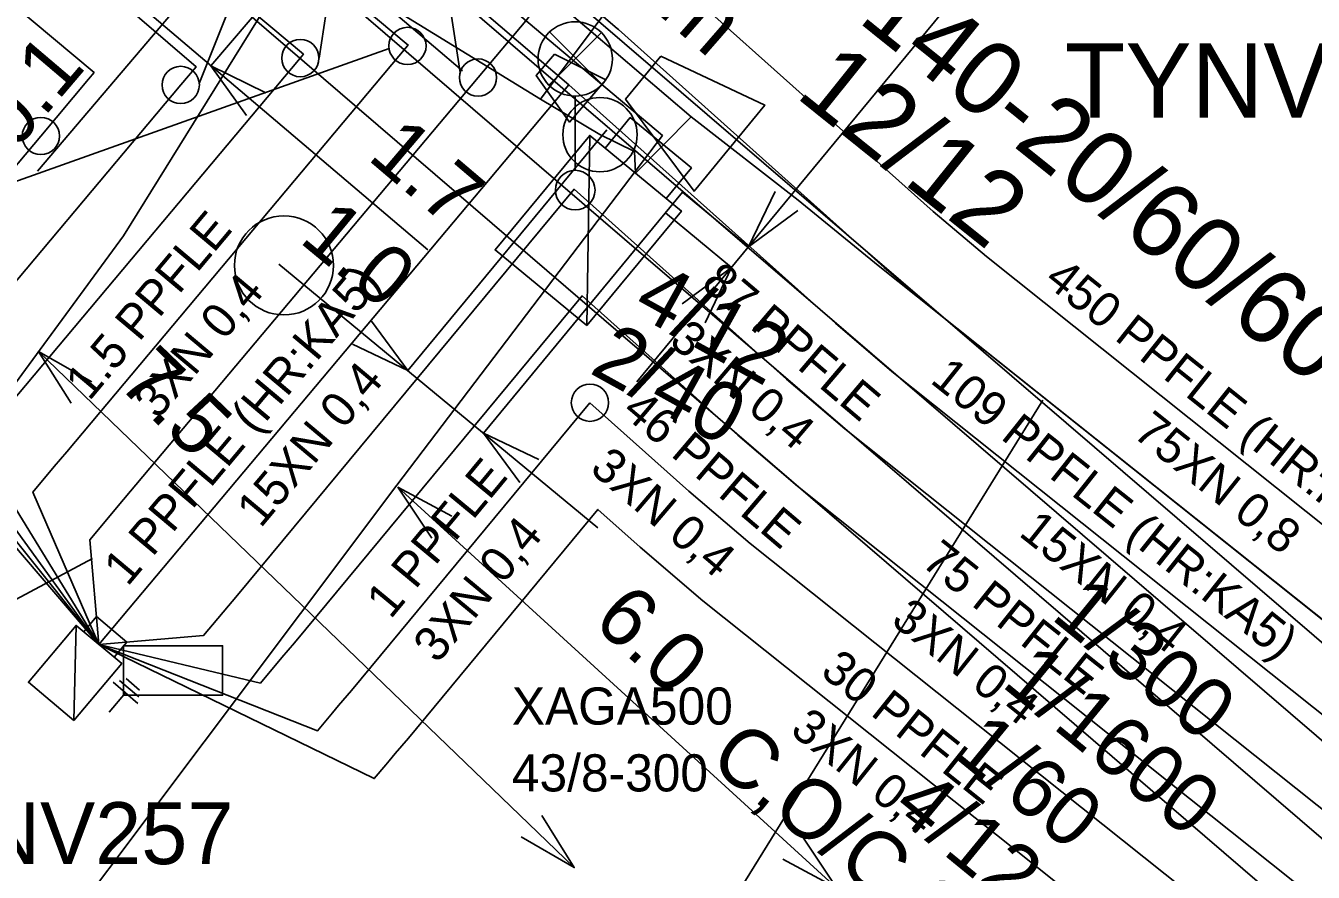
# Model space of a CAD drawing. Extents: x -756413 to -755757, y -1139003 to -1138237.
# Drawn here: x -756288.54 to -756275.54, y -1138383.61 to -1138375.06 of the extents above; entities that cross this region are included whole.
import ezdxf

# ---------------------------------------------------------------- set-up
doc = ezdxf.new("R2010")
doc.units = 0
for name, color, linetype in [('f002_inz_znacky_mimo_TO2', 7, 'Continuous'), ('f003_opt_sit_texty', 7, 'Continuous'), ('f004_popis_kab_zil', 7, 'Continuous'), ('f004_popisy_mts', 7, 'Continuous'), ('f004_rezervy_spojky', 7, 'Continuous'), ('f004_rozvadec', 7, 'Continuous'), ('f004_rozvadec_ann', 7, 'Continuous'), ('f006_osa_trasy', 7, 'Continuous'), ('f006_stp_koty', 7, 'Continuous'), ('f006_stp_linie', 7, 'Continuous'), ('f006_stp_texty', 7, 'Continuous'), ('f007_rezkynet_linie', 7, 'Continuous'), ('f307_kabel_metal', 7, 'Continuous'), ('f307_kabel_metal_ann', 7, 'Continuous'), ('f307_ost_bod_obj_met', 7, 'Continuous'), ('f307_rozvadec', 7, 'Continuous'), ('f307_rozvadec_ann', 7, 'Continuous'), ('f307_spojka_metal', 7, 'Continuous'), ('f307_spojka_metal_ann', 7, 'Continuous'), ('f309_trubka', 7, 'Continuous'), ('f373_cerch_cara', 7, 'Continuous')]:
    doc.layers.add(name, color=color, linetype=linetype)

msp = doc.modelspace()

# ---------------------------------------------------------------- linework, layer by layer
at = {"layer": 'f002_inz_znacky_mimo_TO2'}
for p, q in [((-756282.718, -1138375.655), (-756283.246, -1138375.126)), ((-756283.254, -1138375.658), (-756282.726, -1138375.13)), ((-756282.99, -1138375.77), (-756282.99, -1138376.52))]:
    msp.add_line(p, q, dxfattribs=at)
msp.add_lwpolyline([(-756287.55, -1138381.82), (-756286.55, -1138381.82), (-756286.55, -1138381.32), (-756287.55, -1138381.32)], close=True, dxfattribs=at)
for centre, radius in [((-756282.99, -1138375.395), 0.375), ((-756282.99, -1138376.72), 0.2), ((-756285.93, -1138377.48), 0.5)]:
    msp.add_circle(centre, radius, dxfattribs=at)
at = {"layer": 'f004_rezervy_spojky'}
msp.add_lwpolyline([(-756282.125, -1138375.366), (-756281.077, -1138375.862), (-756281.79, -1138376.732), (-756282.482, -1138375.801)], close=True, dxfattribs=at)
msp.add_circle((-756282.74, -1138376.16), 0.375, dxfattribs=at)
at = {"layer": 'f004_rozvadec'}
msp.add_line((-756282.873, -1138378.088), (-756282.843, -1138376.168), dxfattribs=at)
msp.add_lwpolyline([(-756282.688, -1138376.295), (-756282.434, -1138375.987), (-756281.817, -1138376.496), (-756282.072, -1138376.805)], dxfattribs=at)
msp.add_lwpolyline([(-756282.873, -1138378.088), (-756283.798, -1138377.324), (-756282.843, -1138376.168), (-756281.917, -1138376.932)], close=True, dxfattribs=at)
at = {"layer": 'f006_osa_trasy'}
for p, q in [((-756278.21, -1138368.9), (-756282.83, -1138375.12)), ((-756282.83, -1138375.12), (-756283.34, -1138375.8)), ((-756281.82, -1138375.98), (-756282.83, -1138375.12)), ((-756283.34, -1138375.8), (-756282.74, -1138376.16)), ((-756281.82, -1138375.98), (-756282.38, -1138376.55))]:
    msp.add_line(p, q, dxfattribs=at)
for points in [[(-756282.83, -1138375.12), (-756286.84, -1138371.72), (-756290.36, -1138368.73), (-756302.28, -1138358.38), (-756303.67, -1138357.72), (-756311.7, -1138350.6)], [(-756290.62, -1138387.46), (-756284.79, -1138379.7), (-756282.11, -1138376.17), (-756288.02, -1138371.19), (-756301.12, -1138358.98), (-756302.2, -1138358.1), (-756303.05, -1138358.15), (-756304.87, -1138359.66)], [(-756312.22, -1138404.34), (-756311.43, -1138403.06), (-756307.8, -1138399.78), (-756302.65, -1138394.53), (-756298.44, -1138390.08), (-756293.77, -1138384.84), (-756291.02, -1138381.91), (-756287.55, -1138377.18), (-756286, -1138374.68), (-756285.31, -1138374.59), (-756283.34, -1138375.8)], [(-756272.52, -1138383.39), (-756279.93, -1138377.48), (-756280.74, -1138376.82), (-756281.82, -1138375.98)], [(-756282.74, -1138376.16), (-756282.39, -1138376.33), (-756282.38, -1138376.55)]]:
    msp.add_lwpolyline(points, dxfattribs=at)
at = {"layer": 'f006_stp_koty'}
for p, q in [((-756289.262, -1138371.148), (-756284.127, -1138375.514)), ((-756288.418, -1138376.529), (-756285.145, -1138372.679)), ((-756284.479, -1138377.324), (-756289.103, -1138373.393)), ((-756282.367, -1138378.657), (-756278.169, -1138373.576)), ((-756286, -1138374.68), (-756286.667, -1138375.464)), ((-756282.67, -1138376.11), (-756284.681, -1138378.543)), ((-756281.907, -1138376.741), (-756283.917, -1138379.174)), ((-756281.907, -1138376.741), (-756281.239, -1138377.292)), ((-756282.08, -1138376.95), (-756281.412, -1138377.501)), ((-756285.981, -1138377.468), (-756282.761, -1138380.129)), ((-756283, -1138383.56), (-756288.408, -1138378.349)), ((-756280.35, -1138383.77), (-756284.779, -1138379.72))]:
    msp.add_line(p, q, dxfattribs=at)
for points in [[(-756286.307, -1138375.966), (-756286.667, -1138375.464), (-756286.112, -1138375.738)], [(-756280.741, -1138376.925), (-756281.239, -1138377.292), (-756280.972, -1138376.733)], [(-756281.909, -1138377.867), (-756281.412, -1138377.501), (-756281.678, -1138378.059)], [(-756285.047, -1138378.045), (-756284.681, -1138378.543), (-756285.239, -1138378.276)], [(-756288.079, -1138378.873), (-756288.408, -1138378.349), (-756287.871, -1138378.657)], [(-756283.55, -1138379.671), (-756283.917, -1138379.174), (-756283.358, -1138379.44)], [(-756284.437, -1138380.235), (-756284.779, -1138379.72), (-756284.234, -1138380.014)], [(-756283.328, -1138383.035), (-756283, -1138383.56), (-756283.536, -1138383.251)], [(-756280.691, -1138383.254), (-756280.35, -1138383.77), (-756280.894, -1138383.475)]]:
    msp.add_lwpolyline(points, dxfattribs=at)
at = {"layer": 'f006_stp_linie'}
msp.add_line((-756282.74, -1138376.16), (-756282.39, -1138376.33), dxfattribs=at)
for points in [[(-756278.21, -1138368.9), (-756282.83, -1138375.12), (-756283.34, -1138375.8)], [(-756286.84, -1138371.72), (-756282.83, -1138375.12), (-756281.82, -1138375.98), (-756280.74, -1138376.82)], [(-756325.53, -1138418.96), (-756324.32, -1138416.51), (-756322.61, -1138413.84), (-756321.49, -1138412.22), (-756320.41, -1138411.21), (-756318.19, -1138409.32), (-756315.85, -1138407.31), (-756315.25, -1138406.9), (-756313.95, -1138405.81), (-756312.72, -1138405.17), (-756312.44, -1138404.71), (-756312.22, -1138404.34), (-756311.43, -1138403.06), (-756307.8, -1138399.78), (-756302.65, -1138394.53), (-756298.44, -1138390.08), (-756293.77, -1138384.84), (-756291.02, -1138381.91), (-756287.55, -1138377.18), (-756286, -1138374.68), (-756285.31, -1138374.59), (-756283.34, -1138375.8), (-756282.74, -1138376.16)], [(-756279.93, -1138377.48), (-756272.52, -1138383.39), (-756268.72, -1138385.93), (-756262.4, -1138389.61), (-756257.5, -1138391.97), (-756251.81, -1138394.29), (-756243.07, -1138396.46), (-756234.47, -1138397.8), (-756219.38, -1138400.15), (-756214.62, -1138400.84), (-756208.37, -1138401.82)]]:
    msp.add_lwpolyline(points, dxfattribs=at)
at = {"layer": 'f007_rezkynet_linie'}
msp.add_line((-756286.89, -1138392.77), (-756278.27, -1138378.84), dxfattribs=at)
at = {"layer": 'f307_kabel_metal'}
for p, q in [((-756312.023, -1138350.844), (-756283.054, -1138375.657)), ((-756283.054, -1138375.657), (-756287.798, -1138381.308))]:
    msp.add_line(p, q, dxfattribs=at)
for points in [[(-756310.454, -1138350.213), (-756282.069, -1138374.526), (-756282.051, -1138374.542), (-756279.377, -1138376.935), (-756278.838, -1138377.392), (-756272.1, -1138382.766), (-756271.532, -1138383.148), (-756268.323, -1138385.294), (-756262.071, -1138388.934), (-756261.451, -1138389.235), (-756257.195, -1138391.284), (-756251.577, -1138393.575), (-756242.922, -1138395.724), (-756234.355, -1138397.059), (-756233.614, -1138397.174), (-756219.271, -1138399.407)], [(-756310.942, -1138350.783), (-756282.566, -1138375.087), (-756282.554, -1138375.098), (-756279.87, -1138377.5), (-756279.315, -1138377.971), (-756272.544, -1138383.371), (-756271.95, -1138383.771), (-756268.72, -1138385.93), (-756262.424, -1138389.596), (-756261.778, -1138389.91), (-756257.5, -1138391.97), (-756251.81, -1138394.29), (-756243.07, -1138396.46), (-756234.47, -1138397.8), (-756233.729, -1138397.915), (-756219.383, -1138400.149)], [(-756283.971, -1138375.583), (-756283.489, -1138375.009), (-756279.087, -1138369.245), (-756278.124, -1138370.005), (-756278.057, -1138370.064), (-756275.436, -1138372.41), (-756275.026, -1138372.757), (-756270.414, -1138376.436), (-756263.958, -1138368.536)], [(-756284.683, -1138375.264), (-756284.676, -1138375.255), (-756291.577, -1138369.478), (-756295.006, -1138373.564), (-756295.13, -1138373.711), (-756298.544, -1138377.773), (-756318.688, -1138398.187), (-756319.519, -1138397.43)], [(-756285.765, -1138375.387), (-756285.733, -1138375.348), (-756291.484, -1138370.534), (-756294.432, -1138374.047), (-756294.556, -1138374.194), (-756297.989, -1138378.278), (-756318.66, -1138399.227), (-756319.205, -1138399.742), (-756330.074, -1138410.117), (-756326.605, -1138419.746), (-756341.343, -1138432.472)], [(-756286.972, -1138375.658), (-756286.816, -1138375.476), (-756291.179, -1138371.724), (-756291.391, -1138371.59), (-756293.858, -1138374.53), (-756293.982, -1138374.677), (-756297.434, -1138378.783), (-756318.135, -1138399.763), (-756318.689, -1138400.286), (-756329.203, -1138410.322), (-756325.725, -1138419.977), (-756325.47, -1138420.682), (-756325.148, -1138421.576), (-756313.125, -1138448.388), (-756305.964, -1138469.586), (-756306.39, -1138472.389), (-756307.168, -1138474.638), (-756308.162, -1138475.59), (-756309.285, -1138475.849), (-756315.462, -1138479.353)], [(-756288.384, -1138376.174), (-756287.902, -1138375.6), (-756287.847, -1138375.534), (-756291.298, -1138372.646), (-756293.284, -1138375.013), (-756293.408, -1138375.16), (-756296.879, -1138379.289), (-756317.519, -1138400.206), (-756328.332, -1138410.527), (-756324.452, -1138421.295), (-756312.811, -1138447.256), (-756304.831, -1138441.703), (-756301.921, -1138444.882), (-756300.466, -1138443.292)], [(-756287.798, -1138381.308), (-756289.039, -1138379.287), (-756288.887, -1138379.105), (-756288.822, -1138379.029), (-756288.697, -1138378.88), (-756285.765, -1138375.387)], [(-756287.798, -1138381.308), (-756288.465, -1138379.769), (-756288.249, -1138379.512), (-756288.123, -1138379.363), (-756284.683, -1138375.264)], [(-756287.798, -1138381.308), (-756287.89, -1138380.251), (-756287.549, -1138379.845), (-756283.971, -1138375.583)], [(-756287.798, -1138381.308), (-756290.762, -1138377.84), (-756290.683, -1138377.744), (-756290.663, -1138377.72), (-756290.644, -1138377.699), (-756290.607, -1138377.654), (-756290.541, -1138377.576), (-756290.421, -1138377.434), (-756288.958, -1138375.692)], [(-756287.798, -1138381.308), (-756289.613, -1138378.805), (-756289.496, -1138378.664), (-756289.46, -1138378.621), (-756289.394, -1138378.544), (-756289.272, -1138378.398), (-756286.972, -1138375.658)], [(-756283.054, -1138375.657), (-756280.363, -1138378.065), (-756279.792, -1138378.55), (-756272.988, -1138383.976), (-756272.368, -1138384.394), (-756269.117, -1138386.566), (-756262.777, -1138390.258), (-756262.105, -1138390.585), (-756257.805, -1138392.656), (-756252.043, -1138395.005), (-756243.218, -1138397.196), (-756234.585, -1138398.541), (-756233.844, -1138398.656), (-756219.495, -1138400.891), (-756218.753, -1138400.999), (-756214.732, -1138401.582), (-756208.498, -1138402.559), (-756199.964, -1138404.184), (-756190.805, -1138406.292), (-756186.311, -1138407.813)], [(-756287.798, -1138381.308), (-756290.188, -1138378.322), (-756290.091, -1138378.206), (-756290.072, -1138378.184), (-756290.032, -1138378.136), (-756289.967, -1138378.059), (-756289.847, -1138377.916), (-756288.384, -1138376.174)], [(-756287.798, -1138381.308), (-756286.741, -1138381.216), (-756286.4, -1138380.81), (-756283.001, -1138376.711), (-756280.856, -1138378.63), (-756280.269, -1138379.129), (-756273.432, -1138384.581), (-756272.786, -1138385.017), (-756269.514, -1138387.202), (-756263.13, -1138390.92), (-756262.432, -1138391.26), (-756258.11, -1138393.342), (-756252.276, -1138395.72), (-756243.366, -1138397.932), (-756234.7, -1138399.282), (-756233.959, -1138399.397), (-756219.607, -1138401.633), (-756219.715, -1138403.938)], [(-756287.798, -1138381.308), (-756286.167, -1138381.698), (-756285.951, -1138381.441), (-756285.824, -1138381.291), (-756282.921, -1138377.789), (-756281.349, -1138379.195), (-756280.746, -1138379.708), (-756273.876, -1138385.186), (-756273.204, -1138385.64), (-756269.911, -1138387.839), (-756263.483, -1138391.582), (-756262.759, -1138391.935), (-756258.415, -1138394.028), (-756252.509, -1138396.435), (-756243.514, -1138398.668), (-756234.815, -1138400.023), (-756234.827, -1138399.997), (-756234.95, -1138400.65), (-756236.72, -1138403.56), (-756242.2, -1138408.96), (-756243.304, -1138410.025)], [(-756287.798, -1138381.308), (-756285.593, -1138382.18), (-756285.44, -1138381.998), (-756285.378, -1138381.925), (-756285.249, -1138381.773), (-756282.841, -1138378.867)], [(-756282.841, -1138378.867), (-756281.842, -1138379.76), (-756281.223, -1138380.287), (-756274.32, -1138385.791), (-756273.622, -1138386.263), (-756270.308, -1138388.476), (-756264.16, -1138392.056), (-756266.339, -1138395.376)], [(-756287.798, -1138381.308), (-756285.018, -1138382.662), (-756284.901, -1138382.522), (-756284.867, -1138382.482), (-756284.806, -1138382.41), (-756284.674, -1138382.255), (-756282.76, -1138379.945), (-756282.335, -1138380.325), (-756281.7, -1138380.866), (-756275.574, -1138385.75), (-756278.058, -1138387.734)]]:
    msp.add_lwpolyline(points, dxfattribs=at)
at = {"layer": 'f307_ost_bod_obj_met'}
for p, q in [((-756287.405, -1138381.904), (-756287.655, -1138381.69)), ((-756287.396, -1138381.836), (-756287.589, -1138381.671)), ((-756287.388, -1138381.768), (-756287.524, -1138381.653)), ((-756287.53, -1138381.797), (-756287.696, -1138381.991))]:
    msp.add_line(p, q, dxfattribs=at)
at = {"layer": 'f307_rozvadec'}
msp.add_line((-756288.05, -1138382.075), (-756288.028, -1138381.115), dxfattribs=at)
msp.add_lwpolyline([(-756287.951, -1138381.179), (-756287.823, -1138381.026), (-756287.516, -1138381.283), (-756287.645, -1138381.437)], dxfattribs=at)
msp.add_lwpolyline([(-756288.05, -1138382.075), (-756288.51, -1138381.69), (-756288.028, -1138381.115), (-756287.568, -1138381.501)], close=True, dxfattribs=at)
at = {"layer": 'f307_spojka_metal'}
msp.add_lwpolyline([(-756283.2, -1138375.347), (-756282.681, -1138375.606), (-756283.047, -1138376.033), (-756283.383, -1138375.561)], close=True, dxfattribs=at)
for centre in [(-756284.683, -1138375.264), (-756285.765, -1138375.387), (-756286.972, -1138375.658), (-756283.971, -1138375.583), (-756288.384, -1138376.174), (-756282.841, -1138378.867)]:
    msp.add_circle(centre, 0.188, dxfattribs=at)
at = {"layer": 'f309_trubka'}
for points in [[(-756310.552, -1138351.565), (-756303.608, -1138357.783), (-756301.98, -1138358.543), (-756289.41, -1138369.29), (-756273.581, -1138382.899), (-756267.391, -1138386.699), (-756260.769, -1138390.604), (-756251.313, -1138394.329), (-756242.348, -1138396.659), (-756226.133, -1138399.092), (-756211.588, -1138401.296), (-756190.711, -1138405.458), (-756180.192, -1138409.372), (-756170.888, -1138414.389), (-756161.932, -1138421.301), (-756154.261, -1138427.534)], [(-756311.061, -1138352.116), (-756304.026, -1138358.416), (-756302.39, -1138359.179), (-756289.898, -1138369.859), (-756274.024, -1138383.507), (-756267.778, -1138387.342), (-756261.099, -1138391.28), (-756251.546, -1138395.043), (-756242.498, -1138397.395), (-756226.245, -1138399.834), (-756211.718, -1138402.035), (-756190.916, -1138406.182), (-756180.502, -1138410.057), (-756171.298, -1138415.02), (-756162.398, -1138421.889), (-756154.878, -1138427.999)], [(-756311.57, -1138352.667), (-756304.444, -1138359.049), (-756302.8, -1138359.815), (-756290.386, -1138370.428), (-756274.468, -1138384.115), (-756268.165, -1138387.985), (-756261.429, -1138391.956), (-756251.779, -1138395.757), (-756242.648, -1138398.131), (-756226.357, -1138400.576), (-756211.848, -1138402.774), (-756191.121, -1138406.906), (-756180.812, -1138410.742), (-756171.708, -1138415.651), (-756162.864, -1138422.477), (-756155.495, -1138428.464)], [(-756312.079, -1138353.218), (-756304.862, -1138359.682), (-756303.21, -1138360.452), (-756290.874, -1138370.997), (-756274.912, -1138384.723), (-756268.552, -1138388.628), (-756261.759, -1138392.632), (-756252.012, -1138396.471), (-756242.798, -1138398.867), (-756226.469, -1138401.318), (-756211.978, -1138403.513), (-756191.326, -1138407.63), (-756181.122, -1138411.427), (-756172.118, -1138416.282), (-756163.33, -1138423.065), (-756156.112, -1138428.929), (-756154.994, -1138431.554)]]:
    msp.add_lwpolyline(points, dxfattribs=at)
at = {"layer": 'f373_cerch_cara'}
for p in [(-756286.785, -1138375.642), (-756285.576, -1138375.389)]:
    msp.add_line(p, (-756284.874, -1138370.831), dxfattribs=at)
for points in [[(-756284.151, -1138375.531), (-756284.874, -1138370.831), (-756281.608, -1138370.792)], [(-756284.867, -1138375.29), (-756290.484, -1138377.288), (-756290.935, -1138377.287)], [(-756287.861, -1138380.439), (-756291.887, -1138382.589), (-756295.017, -1138382.609)]]:
    msp.add_lwpolyline(points, dxfattribs=at)

# ---------------------------------------------------------------- texts
at = {"layer": 'f003_opt_sit_texty'}
msp.add_text('C,O/C,C/O', height=0.6, rotation=321.43, dxfattribs=at).set_placement((-756281.66, -1138382.51))
at = {"layer": 'f004_popis_kab_zil'}
for s, rotation, p in [('4/12', 331, (-756282.43, -1138377.95)), ('2/40', 331, (-756282.86, -1138378.56)), ('1/300', 320.67, (-756278.2, -1138381.04)), ('1/1600', 320.67, (-756278.7, -1138381.72)), ('1/60', 320.67, (-756279.2, -1138382.42)), ('4/12', 320.67, (-756279.81, -1138382.99))]:
    msp.add_text(s, height=0.6, rotation=rotation, dxfattribs=at).set_placement(p)
at = {"layer": 'f004_popisy_mts'}
for s, p in [('140-20/60/60', (-756280.15, -1138375.01)), ('12/12', (-756280.78, -1138375.77))]:
    msp.add_text(s, height=0.75, rotation=321.28, dxfattribs=at).set_placement(p)
at = {"layer": 'f004_rozvadec_ann'}
msp.add_text('TYNV257', height=0.75, dxfattribs=at).set_placement((-756278.049, -1138375.987))
at = {"layer": 'f006_stp_koty'}
for s, rotation, p in [('0.1', 49.63, (-756288.645, -1138376.334)), ('1.7', 319.63, (-756285.1, -1138376.401)), ('1.0', 320.43, (-756285.789, -1138377.236)), ('7.5', 316.07, (-756287.626, -1138378.684)), ('6.0', 317.57, (-756282.827, -1138381.096))]:
    msp.add_text(s, height=0.6, rotation=rotation, dxfattribs=at).set_placement(p)
at = {"layer": 'f006_stp_texty'}
msp.add_text('3xPE125 10m', height=0.65, rotation=318.91, dxfattribs=at).set_placement((-756285.75, -1138371.81))
at = {"layer": 'f307_kabel_metal_ann'}
for s, rotation, p in [('1.5 PPFLE', 50, (-756287.895, -1138378.858)), ('1 PPFLE (HR:KA5)', 49.99, (-756287.509, -1138380.731)), (' 3XN 0,4', 50, (-756287.286, -1138379.144)), ('87 PPFLE', 319.63, (-756281.732, -1138377.689)), ('450 PPFLE (HR:KA7)', 321.43, (-756278.269, -1138377.655)), (' 3XN 0,4', 319.63, (-756282.154, -1138378.183)), (' 15XN 0,4', 49.99, (-756286.249, -1138380.241)), ('109 PPFLE (HR:KA5)', 321.43, (-756279.418, -1138378.657)), ('46 PPFLE', 319.59, (-756282.531, -1138378.976)), (' 75XN 0,8', 321.43, (-756277.476, -1138379.118)), (' 3XN 0,4', 319.59, (-756282.954, -1138379.47)), ('1 PPFLE', 50.35, (-756284.854, -1138381.061)), (' 3XN 0,4', 50.35, (-756284.465, -1138381.61)), (' 15XN 0,4', 321.43, (-756278.625, -1138380.12)), ('75 PPFLE', 321.43, (-756279.51, -1138380.501)), (' 3XN 0,4', 321.43, (-756279.917, -1138381.008)), ('30 PPFLE', 321.44, (-756280.528, -1138381.608)), (' 3XN 0,4', 321.44, (-756280.935, -1138382.116))]:
    msp.add_text(s, height=0.35, rotation=rotation, dxfattribs=at).set_placement(p)
at = {"layer": 'f307_rozvadec_ann'}
msp.add_text('TYNV257', height=0.625, dxfattribs=at).set_placement((-756290.064, -1138383.526))
at = {"layer": 'f307_spojka_metal_ann'}
for s, p in [('XAGA500', (-756283.629, -1138382.117)), ('43/8-300', (-756283.629, -1138382.792))]:
    msp.add_text(s, height=0.375, dxfattribs=at).set_placement(p)

doc.saveas('drawing.dxf')
